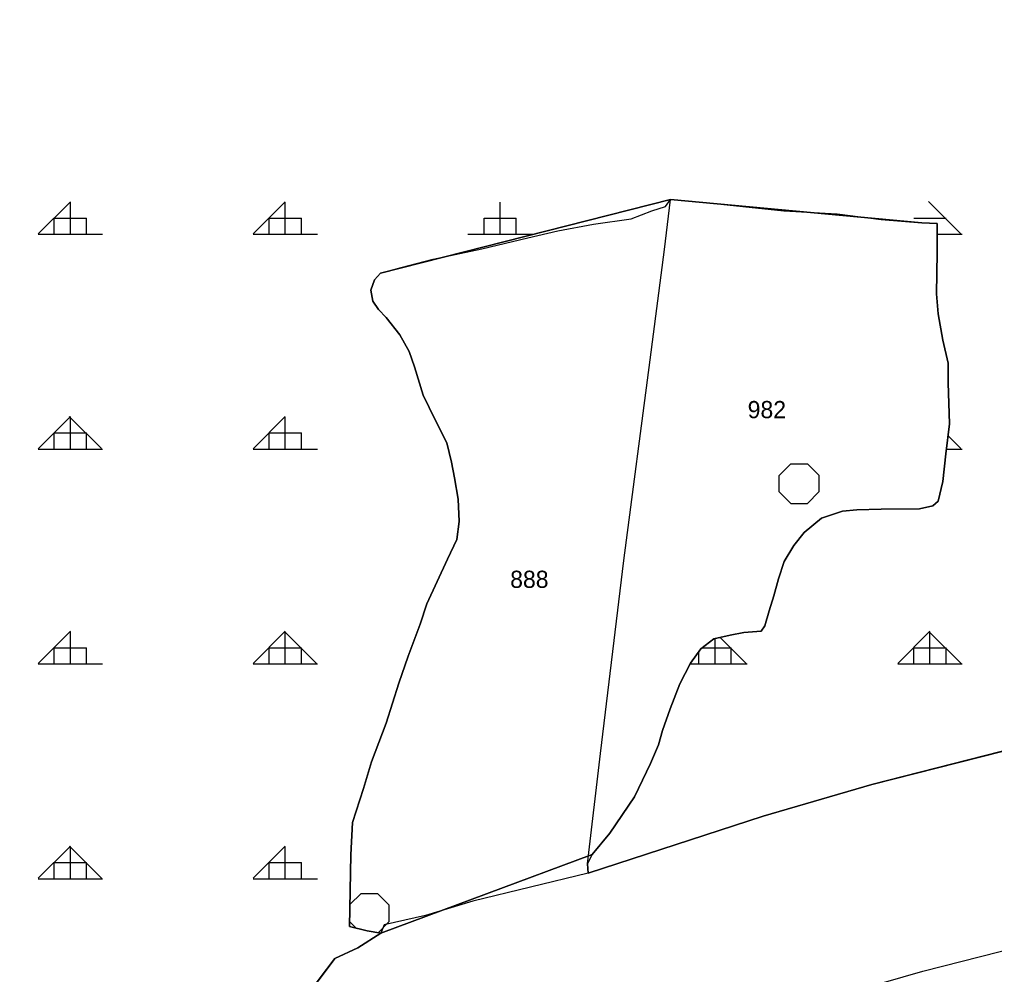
# Model space of a CAD drawing. Extents: x 410727 to 412947, y 4463506 to 4466382.
# Drawn here: x 412400.8 to 412627.7, y 4465413.6 to 4465635.8 of the extents above; entities that cross this region are included whole.
import ezdxf

# ---------------------------------------------------------------- set-up
doc = ezdxf.new("R2010")
doc.units = 0
for name, color, linetype in [('ADAKENARI', 7, 'Continuous'), ('KDS_PARSEL_NO', 7, 'Continuous'), ('KDS_PL', 7, 'Continuous'), ('PL_AYA_ORMAN', 7, 'Continuous'), ('PL_KA_TARIM_DIGER', 7, 'Continuous'), ('SN_ILCE', 7, 'Continuous'), ('TR_ORMAN', 7, 'Continuous'), ('TR_TARIMALANI', 7, 'Continuous')]:
    doc.layers.add(name, color=color, linetype=linetype)

msp = doc.modelspace()

# ---------------------------------------------------------------- linework, layer by layer
at = {"layer": 'ADAKENARI'}
for p, q in [((412552.28, 4465593.94), (412484.83, 4465576.81)), ((412610.81, 4465588.54), (412552.28, 4465593.94)), ((412614.34, 4465588.35), (412610.81, 4465588.54)), ((412614.34, 4465581.56), (412614.34, 4465588.35)), ((412614.16, 4465571.97), (412614.34, 4465581.56)), ((412484.83, 4465576.81), (412483.44, 4465575.23)), ((412483.44, 4465575.23), (412482.6, 4465572.81)), ((412482.6, 4465572.81), (412483.07, 4465570.29)), ((412614.62, 4465567.31), (412614.16, 4465571.97)), ((412483.07, 4465570.29), (412484.37, 4465568.34)), ((412484.37, 4465568.34), (412486.13, 4465566.48)), ((412615.64, 4465561.17), (412614.62, 4465567.31)), ((412486.13, 4465566.48), (412489.29, 4465562.47)), ((412489.29, 4465562.47), (412491.52, 4465558.56)), ((412616.94, 4465555.86), (412615.64, 4465561.17)), ((412491.52, 4465558.56), (412492.73, 4465555.03)), ((412616.94, 4465551.3), (412616.94, 4465555.86)), ((412492.73, 4465555.03), (412494.78, 4465548.42)), ((412617.22, 4465541.71), (412616.94, 4465551.3)), ((412494.78, 4465548.42), (412497.56, 4465542.65)), ((412494.78, 4465548.42), (412497.56, 4465542.65)), ((412497.56, 4465542.65), (412500.26, 4465537.34)), ((412616.39, 4465534.73), (412617.22, 4465541.71)), ((412500.26, 4465537.34), (412501.37, 4465532.78)), ((412615.64, 4465528.31), (412616.39, 4465534.73)), ((412501.37, 4465532.78), (412502.02, 4465529.15)), ((412502.02, 4465529.15), (412502.86, 4465524.21)), ((412614.62, 4465523.75), (412615.64, 4465528.31)), ((412502.86, 4465524.21), (412503.14, 4465519)), ((412592.31, 4465521.38), (412595.64, 4465521.68)), ((412595.64, 4465521.68), (412601.33, 4465521.88)), ((412601.33, 4465521.88), (412610.26, 4465521.97)), ((412610.26, 4465521.97), (412613.32, 4465522.63)), ((412613.32, 4465522.63), (412614.62, 4465523.75)), ((412583.38, 4465516.47), (412587.4, 4465519.81)), ((412587.4, 4465519.81), (412592.31, 4465521.38)), ((412503.14, 4465519), (412502.58, 4465514.81)), ((412581.03, 4465513.42), (412583.38, 4465516.47)), ((412502.58, 4465514.81), (412500.44, 4465510.25)), ((412578.77, 4465509.69), (412581.03, 4465513.42)), ((412578.77, 4465509.69), (412581.03, 4465513.42)), ((412500.44, 4465510.25), (412495.61, 4465499.83)), ((412577.4, 4465505.66), (412578.77, 4465509.69)), ((412576.32, 4465501.72), (412577.4, 4465505.66)), ((412575.24, 4465498.19), (412576.32, 4465501.72)), ((412495.61, 4465499.83), (412494.03, 4465495.08)), ((412574.26, 4465494.75), (412575.24, 4465498.19)), ((412494.03, 4465495.08), (412491.24, 4465487.63)), ((412573.38, 4465493.47), (412574.26, 4465494.75)), ((412562.39, 4465491.7), (412566.21, 4465492.58)), ((412566.21, 4465492.58), (412569.35, 4465493.17)), ((412569.35, 4465493.17), (412573.38, 4465493.47)), ((412559.35, 4465489.34), (412562.39, 4465491.7)), ((412491.24, 4465487.63), (412489.11, 4465481.4)), ((412556.99, 4465486), (412559.35, 4465489.34)), ((412556.99, 4465486), (412559.35, 4465489.34)), ((412554.44, 4465481.18), (412556.99, 4465486)), ((412489.11, 4465481.4), (412486.14, 4465472.09)), ((412552.19, 4465475.38), (412554.44, 4465481.18)), ((412550.42, 4465470.37), (412552.19, 4465475.38)), ((412486.14, 4465472.09), (412482.7, 4465463.06)), ((412549.54, 4465467.03), (412550.42, 4465470.37)), ((412644.65, 4465469.38), (412599.17, 4465457.76)), ((412547.67, 4465462.7), (412549.54, 4465467.03)), ((412482.7, 4465463.06), (412480.84, 4465456.82)), ((412543.95, 4465454.94), (412547.67, 4465462.7)), ((412480.84, 4465456.82), (412478.29, 4465448.92)), ((412599.17, 4465457.76), (412573.84, 4465450.42)), ((412538.16, 4465446.48), (412543.95, 4465454.94)), ((412573.84, 4465450.42), (412533.16, 4465437.15)), ((412478.29, 4465448.92), (412477.95, 4465441.42)), ((412534.04, 4465441.47), (412538.16, 4465446.48)), ((412477.95, 4465441.42), (412477.61, 4465424.74)), ((412484.89, 4465423.19), (412534.04, 4465441.47)), ((412532.96, 4465439.31), (412534.04, 4465441.47)), ((412533.16, 4465437.15), (412532.96, 4465439.31)), ((412477.61, 4465424.74), (412481.69, 4465423.71)), ((412484.89, 4465423.19), (412479.57, 4465419.8)), ((412481.69, 4465423.71), (412484.89, 4465423.19)), ((412479.57, 4465419.8), (412474.23, 4465417.27)), ((412474.23, 4465417.27), (412459.9, 4465398.41))]:
    msp.add_line(p, q, dxfattribs=at)
at = {"layer": 'KDS_PL'}
for p, q in [((412547.92, 4465591.33), (412551.17, 4465592.35)), ((412550.92, 4465582.29), (412552.28, 4465593.94)), ((412551.17, 4465592.35), (412552.28, 4465593.94)), ((412552.28, 4465593.94), (412558.14, 4465593.47)), ((412558.14, 4465593.47), (412578.67, 4465591.33)), ((412543.18, 4465589.47), (412547.92, 4465591.33)), ((412578.67, 4465591.33), (412591.12, 4465590.59)), ((412591.12, 4465590.59), (412601.34, 4465589.28)), ((412526.08, 4465586.68), (412534.35, 4465588.17)), ((412534.35, 4465588.17), (412543.18, 4465589.47)), ((412601.34, 4465589.28), (412610.81, 4465588.54)), ((412610.81, 4465588.54), (412614.34, 4465588.35)), ((412614.34, 4465588.35), (412614.34, 4465581.56)), ((412519.11, 4465585), (412526.08, 4465586.68)), ((412508.43, 4465582.49), (412519.11, 4465585)), ((412497.1, 4465580.07), (412508.43, 4465582.49)), ((412547.57, 4465556.63), (412550.92, 4465582.29)), ((412614.34, 4465581.56), (412614.16, 4465571.97)), ((412489.67, 4465578.11), (412497.1, 4465580.07)), ((412483.44, 4465575.23), (412484.83, 4465576.81)), ((412484.83, 4465576.81), (412489.67, 4465578.11)), ((412482.6, 4465572.81), (412483.44, 4465575.23)), ((412483.07, 4465570.29), (412482.6, 4465572.81)), ((412614.16, 4465571.97), (412614.62, 4465567.31)), ((412484.37, 4465568.34), (412483.07, 4465570.29)), ((412486.13, 4465566.48), (412484.37, 4465568.34)), ((412614.62, 4465567.31), (412615.64, 4465561.17)), ((412489.29, 4465562.47), (412486.13, 4465566.48)), ((412491.52, 4465558.56), (412489.29, 4465562.47)), ((412615.64, 4465561.17), (412616.94, 4465555.86)), ((412492.73, 4465555.03), (412491.52, 4465558.56)), ((412541.47, 4465509.89), (412547.57, 4465556.63)), ((412616.94, 4465555.86), (412616.94, 4465551.3)), ((412494.78, 4465548.42), (412492.73, 4465555.03)), ((412616.94, 4465551.3), (412617.22, 4465541.71)), ((412497.56, 4465542.65), (412494.78, 4465548.42)), ((412500.26, 4465537.34), (412497.56, 4465542.65)), ((412617.22, 4465541.71), (412616.39, 4465534.73)), ((412501.37, 4465532.78), (412500.26, 4465537.34)), ((412616.39, 4465534.73), (412615.64, 4465528.31)), ((412502.02, 4465529.15), (412501.37, 4465532.78)), ((412502.86, 4465524.21), (412502.02, 4465529.15)), ((412615.64, 4465528.31), (412614.62, 4465523.75)), ((412503.14, 4465519), (412502.86, 4465524.21)), ((412595.64, 4465521.68), (412592.31, 4465521.38)), ((412601.33, 4465521.88), (412595.64, 4465521.68)), ((412610.26, 4465521.97), (412601.33, 4465521.88)), ((412613.32, 4465522.63), (412610.26, 4465521.97)), ((412614.62, 4465523.75), (412613.32, 4465522.63)), ((412587.4, 4465519.81), (412583.38, 4465516.47)), ((412592.31, 4465521.38), (412587.4, 4465519.81)), ((412502.58, 4465514.81), (412503.14, 4465519)), ((412583.38, 4465516.47), (412581.03, 4465513.42)), ((412500.44, 4465510.25), (412502.58, 4465514.81)), ((412581.03, 4465513.42), (412578.77, 4465509.69)), ((412495.61, 4465499.83), (412500.44, 4465510.25)), ((412535.98, 4465464.98), (412541.47, 4465509.89)), ((412578.77, 4465509.69), (412577.4, 4465505.66)), ((412577.4, 4465505.66), (412576.32, 4465501.72)), ((412576.32, 4465501.72), (412575.24, 4465498.19)), ((412494.03, 4465495.08), (412495.61, 4465499.83)), ((412575.24, 4465498.19), (412574.26, 4465494.75)), ((412491.24, 4465487.63), (412494.03, 4465495.08)), ((412574.26, 4465494.75), (412573.38, 4465493.47)), ((412566.21, 4465492.58), (412562.39, 4465491.7)), ((412569.35, 4465493.17), (412566.21, 4465492.58)), ((412573.38, 4465493.47), (412569.35, 4465493.17)), ((412562.39, 4465491.7), (412559.35, 4465489.34)), ((412489.11, 4465481.4), (412491.24, 4465487.63)), ((412559.35, 4465489.34), (412556.99, 4465486)), ((412556.99, 4465486), (412554.44, 4465481.18)), ((412486.14, 4465472.09), (412489.11, 4465481.4)), ((412554.44, 4465481.18), (412552.19, 4465475.38)), ((412552.19, 4465475.38), (412550.42, 4465470.37)), ((412482.7, 4465463.06), (412486.14, 4465472.09)), ((412550.42, 4465470.37), (412549.54, 4465467.03)), ((412644.65, 4465469.38), (412599.17, 4465457.76)), ((412532.96, 4465439.31), (412535.98, 4465464.98)), ((412549.54, 4465467.03), (412547.67, 4465462.7)), ((412480.84, 4465456.82), (412482.7, 4465463.06)), ((412547.67, 4465462.7), (412543.95, 4465454.94)), ((412478.29, 4465448.92), (412480.84, 4465456.82)), ((412599.17, 4465457.76), (412573.84, 4465450.42)), ((412543.95, 4465454.94), (412538.16, 4465446.48)), ((412573.84, 4465450.42), (412533.16, 4465437.15)), ((412477.95, 4465441.42), (412478.29, 4465448.92)), ((412538.16, 4465446.48), (412534.04, 4465441.47)), ((412477.61, 4465424.74), (412477.95, 4465441.42)), ((412534.04, 4465441.47), (412532.96, 4465439.31)), ((412532.96, 4465439.31), (412533.16, 4465437.15)), ((412533.16, 4465437.15), (412506.28, 4465430.66)), ((412506.28, 4465430.66), (412495.29, 4465427.32)), ((412495.29, 4465427.32), (412485.68, 4465425.16)), ((412481.69, 4465423.71), (412477.61, 4465424.74)), ((412485.68, 4465425.16), (412484.89, 4465423.19)), ((412479.57, 4465419.8), (412484.89, 4465423.19)), ((412484.89, 4465423.19), (412481.69, 4465423.71)), ((412474.23, 4465417.27), (412479.57, 4465419.8)), ((412459.9, 4465398.41), (412474.23, 4465417.27))]:
    msp.add_line(p, q, dxfattribs=at)
at = {"layer": 'PL_AYA_ORMAN'}
msp.add_lwpolyline([(412459.9, 4465398.41), (412474.23, 4465417.27), (412479.57, 4465419.8), (412484.89, 4465423.19), (412481.69, 4465423.71), (412477.61, 4465424.74), (412477.95, 4465441.42), (412478.29, 4465448.92), (412480.84, 4465456.82), (412482.7, 4465463.06), (412486.14, 4465472.09), (412489.11, 4465481.4), (412491.24, 4465487.63), (412494.03, 4465495.08), (412495.61, 4465499.83), (412500.44, 4465510.25), (412502.58, 4465514.81), (412503.14, 4465519), (412502.86, 4465524.21), (412502.02, 4465529.15), (412501.37, 4465532.78), (412500.26, 4465537.34), (412497.56, 4465542.65), (412494.78, 4465548.42), (412492.73, 4465555.03), (412491.52, 4465558.56), (412489.29, 4465562.47), (412486.13, 4465566.48), (412484.37, 4465568.34), (412483.07, 4465570.29), (412482.6, 4465572.81), (412483.44, 4465575.23), (412484.83, 4465576.81), (412552.28, 4465593.94), (412610.81, 4465588.54), (412614.34, 4465588.35), (412614.34, 4465581.56), (412614.16, 4465571.97), (412614.62, 4465567.31), (412615.64, 4465561.17), (412616.94, 4465555.86), (412616.94, 4465551.3), (412617.22, 4465541.71), (412616.39, 4465534.73), (412615.64, 4465528.31), (412614.62, 4465523.75), (412613.32, 4465522.63), (412610.26, 4465521.97), (412601.33, 4465521.88), (412595.64, 4465521.68), (412592.31, 4465521.38), (412587.4, 4465519.81), (412583.38, 4465516.47), (412581.03, 4465513.42), (412578.77, 4465509.69), (412577.4, 4465505.66), (412576.32, 4465501.72), (412575.24, 4465498.19), (412574.26, 4465494.75), (412573.38, 4465493.47), (412569.35, 4465493.17), (412566.21, 4465492.58), (412562.39, 4465491.7), (412559.35, 4465489.34), (412556.99, 4465486), (412554.44, 4465481.18), (412552.19, 4465475.38), (412550.42, 4465470.37), (412549.54, 4465467.03), (412547.67, 4465462.7), (412543.95, 4465454.94), (412538.16, 4465446.48), (412534.04, 4465441.47), (412532.96, 4465439.31), (412533.16, 4465437.15), (412573.84, 4465450.42), (412599.17, 4465457.76), (412644.65, 4465469.38)], dxfattribs=at)
at = {"layer": 'PL_KA_TARIM_DIGER'}
msp.add_lwpolyline([(412484.83, 4465576.81), (412552.28, 4465593.94), (412610.81, 4465588.54), (412614.34, 4465588.35), (412614.34, 4465581.56), (412614.16, 4465571.97), (412614.62, 4465567.31), (412615.64, 4465561.17), (412616.94, 4465555.86), (412616.94, 4465551.3), (412617.22, 4465541.71), (412616.39, 4465534.73), (412615.64, 4465528.31), (412614.62, 4465523.75), (412613.32, 4465522.63), (412610.26, 4465521.97), (412601.33, 4465521.88), (412595.64, 4465521.68), (412592.31, 4465521.38), (412587.4, 4465519.81), (412583.38, 4465516.47), (412581.03, 4465513.42), (412578.77, 4465509.69), (412577.4, 4465505.66), (412576.32, 4465501.72), (412575.24, 4465498.19), (412574.26, 4465494.75), (412573.38, 4465493.47), (412569.35, 4465493.17), (412566.21, 4465492.58), (412562.39, 4465491.7), (412559.35, 4465489.34), (412556.99, 4465486), (412554.44, 4465481.18), (412552.19, 4465475.38), (412550.42, 4465470.37), (412549.54, 4465467.03), (412547.67, 4465462.7), (412543.95, 4465454.94), (412538.16, 4465446.48), (412534.04, 4465441.47), (412484.89, 4465423.19), (412481.69, 4465423.71), (412477.61, 4465424.74), (412477.95, 4465441.42), (412478.29, 4465448.92), (412480.84, 4465456.82), (412482.7, 4465463.06), (412486.14, 4465472.09), (412489.11, 4465481.4), (412491.24, 4465487.63), (412494.03, 4465495.08), (412495.61, 4465499.83), (412500.44, 4465510.25), (412502.58, 4465514.81), (412503.14, 4465519), (412502.86, 4465524.21), (412502.02, 4465529.15), (412501.37, 4465532.78), (412500.26, 4465537.34), (412497.56, 4465542.65), (412494.78, 4465548.42), (412492.73, 4465555.03), (412491.52, 4465558.56), (412489.29, 4465562.47), (412486.13, 4465566.48), (412484.37, 4465568.34), (412483.07, 4465570.29), (412482.6, 4465572.81), (412483.44, 4465575.23)], close=True, dxfattribs=at)
at = {"layer": 'SN_ILCE'}
msp.add_lwpolyline([(412193.9, 4464682.62), (412249.03, 4464892.07), (412285.26, 4465031.06), (412323.25, 4465172.08), (412447.79, 4465313.34), (412464.51, 4465334.41), (412494.98, 4465370.19), (412502.22, 4465379.72), (412587.08, 4465407.4), (412611.01, 4465414.33), (412655.81, 4465425.78), (412681.09, 4465432.26), (412743.2, 4465445.25), (412753.52, 4465488.83), (412762.98, 4465515.83), (412772.34, 4465544.57), (412788.73, 4465589.26), (412798.93, 4465619.33), (412812.47, 4465658.52), (412814.31, 4465679.77), (412846.88, 4465686.61), (412891.91, 4465700.22), (412906.57, 4465708.44), (412915.37, 4465718.09)], dxfattribs=at)
at = {"layer": 'TR_ORMAN'}
for p, q in [((412405.16, 4465585.94), (412412.66, 4465593.44)), ((412412.67, 4465585.86), (412412.67, 4465593.36)), ((412455.16, 4465585.94), (412462.66, 4465593.44)), ((412462.67, 4465585.86), (412462.67, 4465593.36)), ((412512.67, 4465585.86), (412512.67, 4465593.36)), ((412619.86, 4465585.98), (412612.36, 4465593.48)), ((412408.92, 4465585.86), (412408.92, 4465589.61)), ((412408.92, 4465589.61), (412416.42, 4465589.61)), ((412416.42, 4465585.86), (412416.42, 4465589.61)), ((412458.92, 4465585.86), (412458.92, 4465589.61)), ((412458.92, 4465589.61), (412466.42, 4465589.61)), ((412466.42, 4465585.86), (412466.42, 4465589.61)), ((412508.92, 4465585.86), (412508.92, 4465589.61)), ((412508.92, 4465589.61), (412516.42, 4465589.61)), ((412516.42, 4465585.86), (412516.42, 4465589.61)), ((412608.92, 4465589.61), (412616.42, 4465589.61)), ((412608.92, 4465589.61), (412616.42, 4465589.61)), ((412405.17, 4465585.86), (412420.17, 4465585.86)), ((412455.17, 4465585.86), (412470.17, 4465585.86)), ((412505.17, 4465585.86), (412520.17, 4465585.86)), ((412614.34, 4465585.86), (412620.17, 4465585.86)), ((412614.34, 4465585.86), (412620.17, 4465585.86)), ((412405.16, 4465535.94), (412412.66, 4465543.44)), ((412419.92, 4465535.96), (412412.42, 4465543.46)), ((412412.67, 4465535.86), (412412.67, 4465543.36)), ((412455.16, 4465535.95), (412462.66, 4465543.45)), ((412462.67, 4465535.86), (412462.67, 4465543.36)), ((412408.92, 4465535.86), (412408.92, 4465539.61)), ((412408.92, 4465539.61), (412416.42, 4465539.61)), ((412416.42, 4465535.86), (412416.42, 4465539.61)), ((412458.92, 4465535.86), (412458.92, 4465539.61)), ((412458.92, 4465539.61), (412466.42, 4465539.61)), ((412466.42, 4465535.86), (412466.42, 4465539.61)), ((412619.89, 4465535.96), (412616.89, 4465538.96)), ((412405.17, 4465535.86), (412420.17, 4465535.86)), ((412455.17, 4465535.86), (412470.17, 4465535.86)), ((412616.52, 4465535.86), (412620.17, 4465535.86)), ((412616.52, 4465535.86), (412620.17, 4465535.86)), ((412405.16, 4465485.95), (412412.66, 4465493.45)), ((412405.16, 4465485.95), (412412.66, 4465493.45)), ((412412.67, 4465485.86), (412412.67, 4465493.36)), ((412412.67, 4465485.86), (412412.67, 4465493.36)), ((412455.16, 4465485.96), (412462.66, 4465493.46)), ((412469.94, 4465485.93), (412462.45, 4465493.43)), ((412462.67, 4465485.86), (412462.67, 4465493.36)), ((412605.16, 4465485.98), (412612.66, 4465493.48)), ((412619.92, 4465485.93), (412612.42, 4465493.43)), ((412612.67, 4465485.86), (412612.67, 4465493.36)), ((412562.67, 4465485.86), (412562.67, 4465491.76)), ((412569.93, 4465485.93), (412563.83, 4465492.03)), ((412408.92, 4465485.86), (412408.92, 4465489.61)), ((412408.92, 4465489.61), (412416.42, 4465489.61)), ((412408.92, 4465485.86), (412408.92, 4465489.61)), ((412408.92, 4465489.61), (412416.42, 4465489.61)), ((412416.42, 4465485.86), (412416.42, 4465489.61)), ((412416.42, 4465485.86), (412416.42, 4465489.61)), ((412458.92, 4465485.86), (412458.92, 4465489.61)), ((412458.92, 4465489.61), (412466.42, 4465489.61)), ((412466.42, 4465485.86), (412466.42, 4465489.61)), ((412558.92, 4465485.86), (412558.92, 4465488.73)), ((412559.7, 4465489.61), (412566.42, 4465489.61)), ((412566.42, 4465485.86), (412566.42, 4465489.61)), ((412608.92, 4465485.86), (412608.92, 4465489.61)), ((412608.92, 4465489.61), (412616.42, 4465489.61)), ((412616.42, 4465485.86), (412616.42, 4465489.61)), ((412405.17, 4465485.86), (412420.17, 4465485.86)), ((412405.17, 4465485.86), (412420.17, 4465485.86)), ((412455.17, 4465485.86), (412470.17, 4465485.86)), ((412556.92, 4465485.86), (412570.17, 4465485.86)), ((412605.17, 4465485.86), (412620.17, 4465485.86)), ((412405.16, 4465435.96), (412412.66, 4465443.46)), ((412405.16, 4465435.96), (412412.66, 4465443.46)), ((412419.98, 4465435.91), (412412.48, 4465443.41)), ((412419.98, 4465435.91), (412412.48, 4465443.41)), ((412412.67, 4465435.86), (412412.67, 4465443.36)), ((412412.67, 4465435.86), (412412.67, 4465443.36)), ((412455.16, 4465435.97), (412462.66, 4465443.46)), ((412462.67, 4465435.86), (412462.67, 4465443.36)), ((412408.92, 4465435.86), (412408.92, 4465439.61)), ((412408.92, 4465439.61), (412416.42, 4465439.61)), ((412408.92, 4465435.86), (412408.92, 4465439.61)), ((412408.92, 4465439.61), (412416.42, 4465439.61)), ((412416.42, 4465435.86), (412416.42, 4465439.61)), ((412416.42, 4465435.86), (412416.42, 4465439.61)), ((412458.92, 4465435.86), (412458.92, 4465439.61)), ((412458.92, 4465439.61), (412466.42, 4465439.61)), ((412466.42, 4465435.86), (412466.42, 4465439.61)), ((412405.17, 4465435.86), (412420.17, 4465435.86)), ((412405.17, 4465435.86), (412420.17, 4465435.86)), ((412455.17, 4465435.86), (412470.17, 4465435.86))]:
    msp.add_line(p, q, dxfattribs=at)
at = {"layer": 'TR_TARIMALANI'}
for p, q in [((412577.61, 4465529.73), (412580.31, 4465532.44)), ((412580.32, 4465532.44), (412584.15, 4465532.44)), ((412586.86, 4465529.73), (412584.15, 4465532.44)), ((412577.61, 4465525.9), (412577.61, 4465529.73)), ((412586.86, 4465525.9), (412586.86, 4465529.73)), ((412580.32, 4465523.19), (412577.61, 4465525.9)), ((412584.15, 4465523.19), (412586.85, 4465525.9)), ((412580.32, 4465523.19), (412584.15, 4465523.19)), ((412477.71, 4465429.83), (412480.32, 4465432.44)), ((412480.32, 4465432.44), (412484.15, 4465432.44)), ((412486.86, 4465429.73), (412484.15, 4465432.44)), ((412486.86, 4465425.9), (412486.86, 4465429.73)), ((412479.16, 4465424.35), (412477.63, 4465425.88)), ((412484.25, 4465423.29), (412486.86, 4465425.9))]:
    msp.add_line(p, q, dxfattribs=at)

# ---------------------------------------------------------------- texts
at = {"layer": 'KDS_PARSEL_NO'}
for s, p in [('982', (412570.26, 4465543.05)), ('888', (412515, 4465503.55))]:
    msp.add_text(s, height=4, dxfattribs=at).set_placement(p)

doc.saveas('drawing.dxf')
